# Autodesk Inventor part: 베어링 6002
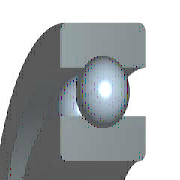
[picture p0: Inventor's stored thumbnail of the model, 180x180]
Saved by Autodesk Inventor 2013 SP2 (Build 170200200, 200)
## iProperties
Created: 2012-02
Part Number: 베어링 6002
Material: 강철, 연강
Description: 깊은 그루브 볼 베어링
Document SubType Name: Modeling
Standard: KS B 2023
Designer: mduedu
Standards Organization: KS
Language: ko-KR
Size Designation: 6002 - 15 x 32 x 9
Categories: <MemberInstance><Categories><Category DisplayName="샤프트 부품" InternalName="7f7aeb1f-a693-4053-b835-cee3144e0d98" Mnemonic="SHFT"><Category DisplayName="베어링" Inter
Density: 7.86 g/cm^3
Mass: 29.8124 g
Surface Area: 39.9079 cm^2
Volume: 3.79293 cm^3
IsCustomPart: 1
Author: mduedu
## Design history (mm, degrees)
sketch "스케치" dims "d0" = 4.42 (= -0.26 x WD + 0.26 x BD)
  geometry: L1 (2.29, 11.75)-(6.71, 11.75); L2 (4.5, 11.75)-(4.5, 9.54); L3 (4.5, 11.75)-(4.5, 13.96); L4 (2.858, 10.271)-(0, 10.271); L5 (0, 7.5)-(9, 7.5); L6 (2.858, 13.229)-(0, 13.229); L7 (0, 16)-(9, 16); L8 (9, 7.5)-(9, 10.271); L9 (6.142, 10.271)-(9, 10.271); L10 (6.142, 13.229)-(9, 13.229); L11 (9, 16)-(9, 13.229); L12 (-1.4, 0)-(8.4, 0) reference; L13 (0, -0.3)-(0, 5.3) reference
  constraints: 22 end point, 4 point on line, 2 collinear, 2 perpendicular, 2 symmetric about line, 1 midpoint, 1 parallel, 14 other
  dimensions: "d9" = 15 diameter of L5 L12 (= WD); "d11" = 32 diameter of L7 L12 (= BD); "d12" = 9 distance between parallel lines of L8 L13 (= KB); "d13" = 20.542 diameter of L9 L12 (= 0.326 x BD + 0.674 x WD)
revolve "본체" stored, may be unused: angle "d6" = 90 deg
revolve "볼" stored, may be unused: angle "d7" = 90 deg
pattern_circular "IDS_ARRAYBALL[SIMPL:T]" dims angle "d3" = 360 deg
body "Solid1"
fillet "모깎기1" dims "d1" = 0.3 (= KRS)
other parameters: "WD" = 15 [user parameter; used in 5 equation terms], "BD" = 32 [user parameter; used in 5 equation terms], "KB" = 9 [user parameter; used in 1 equation term], "KRS" = 0.3 [user parameter; used in 1 equation term], "d4" = 0, "d5" = 0, "d8" = 0, "d14" = 0, "d15" = 0, "BBA" = 0 [user parameter], "BC0" = 2850000 [user parameter], "BC" = 5590000 [user parameter], "BR" = 16 (= 0.5 x BD) [user parameter], "WR" = 7.5 (= 0.5 x WD) [user parameter]
